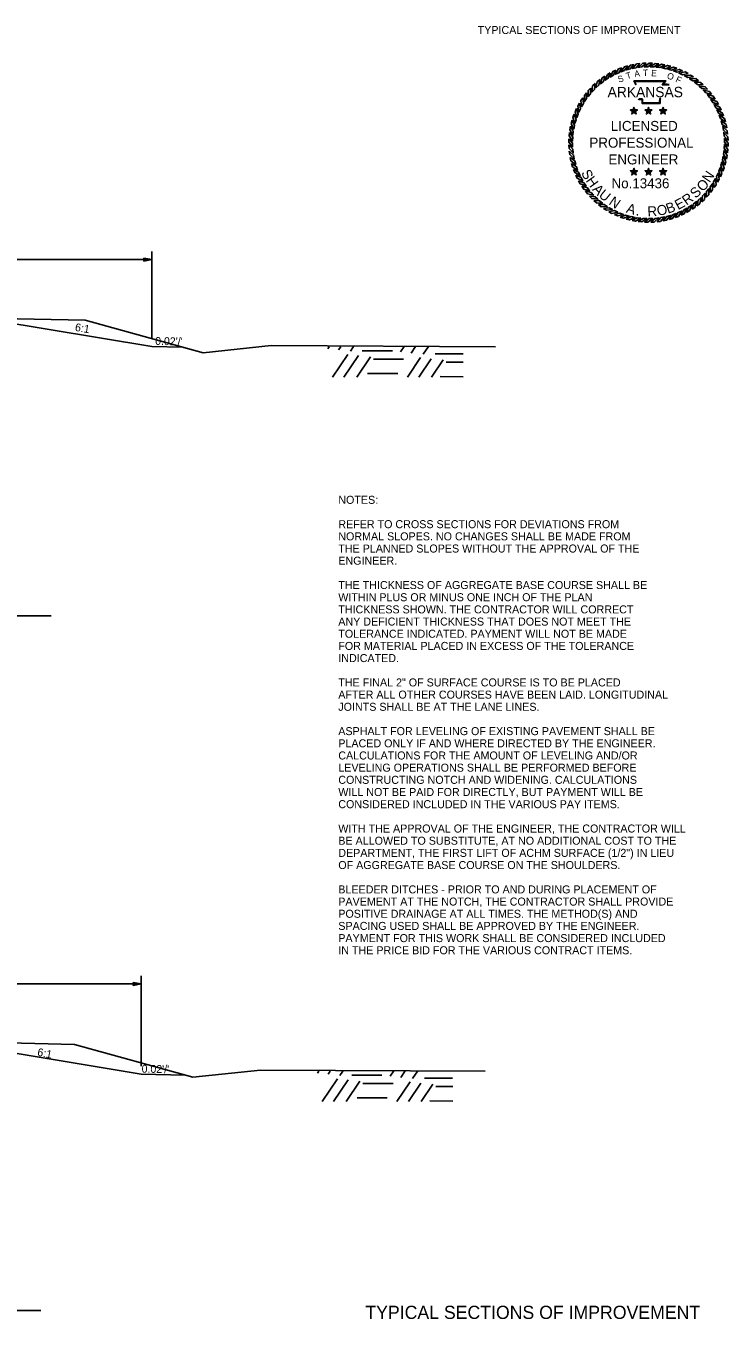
# Model space of a CAD drawing. Extents: x 1398565 to 1398920, y 1968324 to 1968581.
# Drawn here: x 1398867.3 to 1398919.9, y 1968480.4 to 1968577.4 of the extents above; entities that cross this region are included whole.
import ezdxf

# ---------------------------------------------------------------- set-up
doc = ezdxf.new("R2010")
doc.units = 0
for name, color, linetype in [('1', 7, 'Continuous'), ('10', 7, 'Continuous'), ('19', 7, 'Continuous'), ('42', 7, 'Continuous'), ('9', 7, 'Continuous'), ('G-ANNO-SYMB', 7, 'Continuous')]:
    doc.layers.add(name, color=color, linetype=linetype)

msp = doc.modelspace()

# ---------------------------------------------------------------- linework, layer by layer
at = {"layer": '19'}
for p, q in [((1398854.753, 1968559.857), (1398876.753, 1968559.857)), ((1398876.153, 1968559.752), (1398876.153, 1968559.962)), ((1398876.153, 1968559.962), (1398876.753, 1968559.857)), ((1398876.153, 1968559.907), (1398876.593, 1968559.872)), ((1398876.753, 1968559.857), (1398876.153, 1968559.752)), ((1398876.593, 1968559.842), (1398876.153, 1968559.802)), ((1398876.753, 1968553.948), (1398876.753, 1968560.457)), ((1398862.753, 1968555.674), (1398876.753, 1968553.34)), ((1398879.07, 1968553.294), (1398876.753, 1968553.34)), ((1398840.237, 1968533.167), (1398869.217, 1968533.167)), ((1398853.969, 1968505.564), (1398875.969, 1968505.564)), ((1398875.369, 1968505.459), (1398875.369, 1968505.669)), ((1398875.369, 1968505.669), (1398875.969, 1968505.564)), ((1398875.369, 1968505.614), (1398875.809, 1968505.579)), ((1398875.969, 1968505.564), (1398875.369, 1968505.459)), ((1398875.809, 1968505.549), (1398875.369, 1968505.509)), ((1398875.969, 1968499.403), (1398875.969, 1968506.164)), ((1398859.969, 1968501.461), (1398875.969, 1968498.794)), ((1398879.268, 1968498.728), (1398875.969, 1968498.794)), ((1398839.453, 1968481.09), (1398868.433, 1968481.09))]:
    msp.add_line(p, q, dxfattribs=at)
at = {"layer": '42'}
for points in [[(1398854.753, 1968555.787), (1398862.838, 1968555.503), (1398871.753, 1968555.327), (1398880.608, 1968552.866), (1398885.689, 1968553.408), (1398902.506, 1968553.319)], [(1398853.969, 1968501.494), (1398860.054, 1968501.291), (1398870.969, 1968501.034), (1398879.824, 1968498.574), (1398884.905, 1968499.115), (1398901.722, 1968499.026)]]:
    msp.add_lwpolyline(points, dxfattribs=at)
at = {"layer": '9'}
for p, q in [((1398889.943, 1968553.176), (1398890.047, 1968553.33)), ((1398890.292, 1968551.036), (1398891.446, 1968552.752)), ((1398890.741, 1968553.085), (1398890.907, 1968553.332)), ((1398891.631, 1968552.993), (1398891.859, 1968553.333)), ((1398892.521, 1968553.032), (1398894.783, 1968553.018)), ((1398895.394, 1968552.944), (1398895.66, 1968553.34)), ((1398896.192, 1968552.853), (1398896.52, 1968553.341)), ((1398897.082, 1968552.762), (1398897.473, 1968553.343)), ((1398897.972, 1968552.8), (1398900.078, 1968552.787)), ((1398891.152, 1968551.038), (1398892.243, 1968552.661)), ((1398892.105, 1968551.039), (1398893.133, 1968552.569)), ((1398893.356, 1968552.403), (1398895.618, 1968552.388)), ((1398895.906, 1968551.046), (1398896.897, 1968552.52)), ((1398896.766, 1968551.047), (1398897.694, 1968552.429)), ((1398897.718, 1968551.049), (1398898.584, 1968552.338)), ((1398898.807, 1968552.171), (1398900.079, 1968552.163)), ((1398892.913, 1968551.326), (1398895.175, 1968551.312)), ((1398898.364, 1968551.095), (1398900.081, 1968551.084)), ((1398889.159, 1968498.883), (1398889.263, 1968499.037)), ((1398889.508, 1968496.744), (1398890.662, 1968498.459)), ((1398889.957, 1968498.792), (1398890.123, 1968499.039)), ((1398890.847, 1968498.701), (1398891.075, 1968499.041)), ((1398891.737, 1968498.739), (1398893.999, 1968498.725)), ((1398894.611, 1968498.652), (1398894.876, 1968499.047)), ((1398895.408, 1968498.56), (1398895.736, 1968499.049)), ((1398896.298, 1968498.469), (1398896.689, 1968499.05)), ((1398897.188, 1968498.508), (1398899.294, 1968498.494)), ((1398890.368, 1968496.745), (1398891.459, 1968498.368)), ((1398891.321, 1968496.747), (1398892.349, 1968498.277)), ((1398892.572, 1968498.11), (1398894.834, 1968498.096)), ((1398895.122, 1968496.753), (1398896.113, 1968498.228)), ((1398895.982, 1968496.755), (1398896.911, 1968498.136)), ((1398896.934, 1968496.756), (1398897.801, 1968498.045)), ((1398898.023, 1968497.879), (1398899.295, 1968497.87)), ((1398892.129, 1968497.034), (1398894.391, 1968497.019)), ((1398897.58, 1968496.802), (1398899.297, 1968496.791))]:
    msp.add_line(p, q, dxfattribs=at)
at = {"layer": 'G-ANNO-SYMB'}
for points in [[(1398911.524, 1968574.067), (1398911.292, 1968573.957), (1398911.099, 1968573.543), (1398911.342, 1968573.676)], [(1398911.959, 1968574.242), (1398911.719, 1968574.15), (1398911.494, 1968573.752), (1398911.746, 1968573.866)], [(1398912.406, 1968574.382), (1398912.16, 1968574.309), (1398911.904, 1968573.93), (1398912.165, 1968574.024)], [(1398912.862, 1968574.486), (1398912.611, 1968574.433), (1398912.327, 1968574.076), (1398912.594, 1968574.149)], [(1398913.326, 1968574.555), (1398913.071, 1968574.522), (1398912.76, 1968574.187), (1398913.032, 1968574.239)], [(1398913.793, 1968574.586), (1398913.537, 1968574.573), (1398913.2, 1968574.264), (1398913.475, 1968574.295)], [(1398914.262, 1968574.581), (1398914.005, 1968574.589), (1398913.645, 1968574.307), (1398913.922, 1968574.316)], [(1398914.728, 1968574.54), (1398914.473, 1968574.567), (1398914.092, 1968574.315), (1398914.369, 1968574.302)], [(1398915.19, 1968574.461), (1398914.938, 1968574.509), (1398914.538, 1968574.287), (1398914.813, 1968574.252)], [(1398915.644, 1968574.347), (1398915.397, 1968574.414), (1398914.981, 1968574.224), (1398915.252, 1968574.168)], [(1398916.088, 1968574.198), (1398915.847, 1968574.284), (1398915.417, 1968574.127), (1398915.683, 1968574.05)], [(1398916.519, 1968574.014), (1398916.285, 1968574.119), (1398915.844, 1968573.996), (1398916.104, 1968573.898)], [(1398910.321, 1968573.347), (1398910.121, 1968573.186), (1398910.03, 1968572.738), (1398910.235, 1968572.925)], [(1398910.702, 1968573.618), (1398910.491, 1968573.474), (1398910.365, 1968573.034), (1398910.584, 1968573.204)], [(1398911.104, 1968573.859), (1398910.882, 1968573.731), (1398910.722, 1968573.303), (1398910.953, 1968573.455)], [(1398916.934, 1968573.797), (1398916.709, 1968573.92), (1398916.26, 1968573.832), (1398916.511, 1968573.714)], [(1398917.331, 1968573.548), (1398917.116, 1968573.688), (1398916.662, 1968573.636), (1398916.903, 1968573.499)], [(1398917.707, 1968573.268), (1398917.504, 1968573.425), (1398917.047, 1968573.409), (1398917.276, 1968573.253)], [(1398918.06, 1968572.96), (1398917.87, 1968573.132), (1398917.413, 1968573.152), (1398917.629, 1968572.979)], [(1398909.318, 1968572.366), (1398909.162, 1968572.163), (1398909.178, 1968571.706), (1398909.333, 1968571.935)], [(1398909.626, 1968572.719), (1398909.454, 1968572.529), (1398909.434, 1968572.072), (1398909.608, 1968572.288)], [(1398909.961, 1968573.047), (1398909.775, 1968572.871), (1398909.719, 1968572.417), (1398909.909, 1968572.619)], [(1398918.388, 1968572.625), (1398918.212, 1968572.812), (1398917.758, 1968572.868), (1398917.96, 1968572.678)], [(1398918.688, 1968572.266), (1398918.527, 1968572.466), (1398918.079, 1968572.557), (1398918.266, 1968572.352)], [(1398918.959, 1968571.884), (1398918.815, 1968572.096), (1398918.375, 1968572.222), (1398918.545, 1968572.003)], [(1398908.573, 1968571.178), (1398908.468, 1968570.944), (1398908.59, 1968570.503), (1398908.688, 1968570.763)], [(1398908.79, 1968571.593), (1398908.667, 1968571.368), (1398908.754, 1968570.919), (1398908.872, 1968571.17)], [(1398909.039, 1968571.99), (1398908.899, 1968571.775), (1398908.95, 1968571.321), (1398909.088, 1968571.562)], [(1398912.873, 1968570.998), (1398912.934, 1968571.083), (1398912.873, 1968571.271), (1398912.812, 1968571.083)], [(1398913.964, 1968570.998), (1398914.025, 1968571.083), (1398913.964, 1968571.271), (1398913.903, 1968571.083)], [(1398915.055, 1968570.998), (1398915.116, 1968571.083), (1398915.055, 1968571.271), (1398914.993, 1968571.083)], [(1398919.2, 1968571.482), (1398919.072, 1968571.705), (1398918.644, 1968571.865), (1398918.796, 1968571.633)], [(1398919.408, 1968571.062), (1398919.298, 1968571.294), (1398918.884, 1968571.487), (1398919.017, 1968571.245)], [(1398908.239, 1968570.303), (1398908.172, 1968570.056), (1398908.362, 1968569.64), (1398908.418, 1968569.911)], [(1398908.389, 1968570.747), (1398908.303, 1968570.506), (1398908.459, 1968570.076), (1398908.536, 1968570.342)], [(1398912.873, 1968570.998), (1398912.812, 1968571.083), (1398912.613, 1968571.083), (1398912.774, 1968570.966)], [(1398912.873, 1968570.998), (1398912.774, 1968570.966), (1398912.713, 1968570.778), (1398912.873, 1968570.894)], [(1398912.873, 1968570.998), (1398912.972, 1968570.966), (1398913.132, 1968571.083), (1398912.934, 1968571.083)], [(1398912.873, 1968570.998), (1398912.873, 1968570.894), (1398913.033, 1968570.778), (1398912.972, 1968570.966)], [(1398913.964, 1968570.998), (1398913.903, 1968571.083), (1398913.704, 1968571.083), (1398913.865, 1968570.966)], [(1398913.964, 1968570.998), (1398913.865, 1968570.966), (1398913.803, 1968570.778), (1398913.964, 1968570.894)], [(1398913.964, 1968570.998), (1398914.063, 1968570.966), (1398914.223, 1968571.083), (1398914.025, 1968571.083)], [(1398913.964, 1968570.998), (1398913.964, 1968570.894), (1398914.124, 1968570.778), (1398914.063, 1968570.966)], [(1398915.055, 1968570.998), (1398914.993, 1968571.083), (1398914.795, 1968571.083), (1398914.956, 1968570.966)], [(1398915.055, 1968570.998), (1398914.956, 1968570.966), (1398914.894, 1968570.778), (1398915.055, 1968570.894)], [(1398915.055, 1968570.998), (1398915.154, 1968570.966), (1398915.314, 1968571.083), (1398915.116, 1968571.083)], [(1398915.055, 1968570.998), (1398915.055, 1968570.894), (1398915.215, 1968570.778), (1398915.154, 1968570.966)], [(1398919.583, 1968570.628), (1398919.491, 1968570.867), (1398919.093, 1968571.093), (1398919.207, 1968570.84)], [(1398919.723, 1968570.181), (1398919.65, 1968570.427), (1398919.271, 1968570.683), (1398919.365, 1968570.422)], [(1398919.827, 1968569.724), (1398919.774, 1968569.975), (1398919.417, 1968570.26), (1398919.49, 1968569.992)], [(1398908.047, 1968569.387), (1398908.02, 1968569.132), (1398908.272, 1968568.751), (1398908.285, 1968569.028)], [(1398908.125, 1968569.849), (1398908.078, 1968569.597), (1398908.3, 1968569.197), (1398908.334, 1968569.472)], [(1398919.895, 1968569.261), (1398919.863, 1968569.515), (1398919.528, 1968569.827), (1398919.58, 1968569.555)], [(1398919.927, 1968568.793), (1398919.914, 1968569.049), (1398919.605, 1968569.387), (1398919.636, 1968569.111)], [(1398908.005, 1968568.921), (1398907.998, 1968568.664), (1398908.279, 1968568.304), (1398908.271, 1968568.581)], [(1398908, 1968568.452), (1398908.013, 1968568.196), (1398908.322, 1968567.859), (1398908.292, 1968568.134)], [(1398919.881, 1968567.858), (1398919.908, 1968568.113), (1398919.656, 1968568.495), (1398919.643, 1968568.218)], [(1398919.922, 1968568.325), (1398919.93, 1968568.581), (1398919.648, 1968568.942), (1398919.657, 1968568.665)], [(1398908.032, 1968567.985), (1398908.065, 1968567.73), (1398908.399, 1968567.419), (1398908.347, 1968567.691)], [(1398908.1, 1968567.521), (1398908.153, 1968567.27), (1398908.511, 1968566.986), (1398908.438, 1968567.253)], [(1398919.688, 1968566.942), (1398919.755, 1968567.19), (1398919.565, 1968567.606), (1398919.509, 1968567.334)], [(1398919.802, 1968567.396), (1398919.85, 1968567.649), (1398919.628, 1968568.048), (1398919.593, 1968567.773)], [(1398908.205, 1968567.065), (1398908.277, 1968566.819), (1398908.656, 1968566.563), (1398908.562, 1968566.824)], [(1398908.345, 1968566.618), (1398908.436, 1968566.378), (1398908.834, 1968566.153), (1398908.72, 1968566.405)], [(1398912.873, 1968566.43), (1398912.812, 1968566.514), (1398912.613, 1968566.514), (1398912.774, 1968566.398)], [(1398912.873, 1968566.43), (1398912.774, 1968566.398), (1398912.713, 1968566.21), (1398912.873, 1968566.326)], [(1398912.873, 1968566.43), (1398912.934, 1968566.514), (1398912.873, 1968566.703), (1398912.812, 1968566.514)], [(1398912.873, 1968566.43), (1398912.972, 1968566.398), (1398913.132, 1968566.514), (1398912.934, 1968566.514)], [(1398912.873, 1968566.43), (1398912.873, 1968566.326), (1398913.033, 1968566.21), (1398912.972, 1968566.398)], [(1398913.964, 1968566.43), (1398913.903, 1968566.514), (1398913.704, 1968566.514), (1398913.865, 1968566.398)], [(1398913.964, 1968566.43), (1398913.865, 1968566.398), (1398913.803, 1968566.21), (1398913.964, 1968566.326)], [(1398913.964, 1968566.43), (1398914.025, 1968566.514), (1398913.964, 1968566.703), (1398913.903, 1968566.514)], [(1398913.964, 1968566.43), (1398914.063, 1968566.398), (1398914.223, 1968566.514), (1398914.025, 1968566.514)], [(1398913.964, 1968566.43), (1398913.964, 1968566.326), (1398914.124, 1968566.21), (1398914.063, 1968566.398)], [(1398915.055, 1968566.43), (1398914.993, 1968566.514), (1398914.795, 1968566.514), (1398914.956, 1968566.398)], [(1398915.055, 1968566.43), (1398914.956, 1968566.398), (1398914.894, 1968566.21), (1398915.055, 1968566.326)], [(1398915.055, 1968566.43), (1398915.116, 1968566.514), (1398915.055, 1968566.703), (1398914.993, 1968566.514)], [(1398915.055, 1968566.43), (1398915.154, 1968566.398), (1398915.314, 1968566.514), (1398915.116, 1968566.514)], [(1398915.055, 1968566.43), (1398915.055, 1968566.326), (1398915.215, 1968566.21), (1398915.154, 1968566.398)], [(1398919.138, 1968565.652), (1398919.26, 1968565.877), (1398919.173, 1968566.326), (1398919.055, 1968566.075)], [(1398919.355, 1968566.067), (1398919.46, 1968566.301), (1398919.337, 1968566.742), (1398919.239, 1968566.483)], [(1398919.539, 1968566.498), (1398919.625, 1968566.74), (1398919.468, 1968567.169), (1398919.391, 1968566.903)], [(1398908.519, 1968566.183), (1398908.629, 1968565.951), (1398909.044, 1968565.758), (1398908.91, 1968566.001)], [(1398908.728, 1968565.763), (1398908.855, 1968565.541), (1398909.284, 1968565.381), (1398909.131, 1968565.612)], [(1398908.968, 1968565.361), (1398909.113, 1968565.15), (1398909.553, 1968565.024), (1398909.383, 1968565.243)], [(1398918.609, 1968564.879), (1398918.766, 1968565.083), (1398918.75, 1968565.54), (1398918.594, 1968565.31)], [(1398918.889, 1968565.255), (1398919.029, 1968565.47), (1398918.977, 1968565.925), (1398918.84, 1968565.684)], [(1398909.239, 1968564.98), (1398909.4, 1968564.78), (1398909.848, 1968564.689), (1398909.662, 1968564.894)], [(1398909.54, 1968564.62), (1398909.716, 1968564.434), (1398910.17, 1968564.378), (1398909.968, 1968564.568)], [(1398917.607, 1968563.898), (1398917.807, 1968564.059), (1398917.898, 1968564.507), (1398917.693, 1968564.321)], [(1398917.966, 1968564.199), (1398918.153, 1968564.375), (1398918.209, 1968564.829), (1398918.019, 1968564.627)], [(1398918.301, 1968564.526), (1398918.473, 1968564.717), (1398918.493, 1968565.174), (1398918.32, 1968564.957)], [(1398909.867, 1968564.285), (1398910.058, 1968564.113), (1398910.515, 1968564.093), (1398910.298, 1968564.267)], [(1398910.22, 1968563.977), (1398910.424, 1968563.821), (1398910.881, 1968563.837), (1398910.651, 1968563.992)], [(1398910.596, 1968563.698), (1398910.811, 1968563.558), (1398911.266, 1968563.61), (1398911.025, 1968563.747)], [(1398910.993, 1968563.449), (1398911.218, 1968563.326), (1398911.667, 1968563.413), (1398911.416, 1968563.531)], [(1398915.969, 1968563.004), (1398916.208, 1968563.095), (1398916.434, 1968563.493), (1398916.181, 1968563.379)], [(1398916.403, 1968563.178), (1398916.635, 1968563.288), (1398916.828, 1968563.703), (1398916.586, 1968563.569)], [(1398916.823, 1968563.387), (1398917.046, 1968563.514), (1398917.206, 1968563.943), (1398916.974, 1968563.79)], [(1398917.225, 1968563.627), (1398917.437, 1968563.772), (1398917.563, 1968564.212), (1398917.344, 1968564.042)], [(1398911.408, 1968563.232), (1398911.642, 1968563.127), (1398912.083, 1968563.249), (1398911.824, 1968563.347)], [(1398911.839, 1968563.048), (1398912.081, 1968562.962), (1398912.51, 1968563.118), (1398912.244, 1968563.195)], [(1398912.283, 1968562.898), (1398912.531, 1968562.831), (1398912.947, 1968563.021), (1398912.675, 1968563.077)], [(1398912.737, 1968562.784), (1398912.99, 1968562.737), (1398913.389, 1968562.959), (1398913.114, 1968562.993)], [(1398913.199, 1968562.706), (1398913.454, 1968562.679), (1398913.836, 1968562.931), (1398913.559, 1968562.944)], [(1398913.666, 1968562.664), (1398913.922, 1968562.657), (1398914.283, 1968562.938), (1398914.006, 1968562.93)], [(1398914.134, 1968562.659), (1398914.39, 1968562.672), (1398914.728, 1968562.981), (1398914.452, 1968562.951)], [(1398914.602, 1968562.691), (1398914.856, 1968562.724), (1398915.168, 1968563.058), (1398914.896, 1968563.006)], [(1398915.065, 1968562.759), (1398915.316, 1968562.812), (1398915.601, 1968563.17), (1398915.333, 1968563.097)], [(1398915.522, 1968562.864), (1398915.768, 1968562.936), (1398916.024, 1968563.315), (1398915.763, 1968563.221)]]:
    msp.add_lwpolyline(points, close=True, dxfattribs=at)
for points in [[(1398913.008, 1968572.953), (1398912.869, 1968573.254), (1398915.275, 1968573.255), (1398915.074, 1968573.003), (1398915.238, 1968573.005), (1398915.374, 1968573.007), (1398915.511, 1968572.992)], [(1398913.043, 1968572.969), (1398912.928, 1968573.216), (1398915.196, 1968573.217), (1398914.994, 1968572.964), (1398915.238, 1968572.967), (1398915.372, 1968572.968), (1398915.507, 1968572.954)], [(1398914.896, 1968571.944), (1398914.855, 1968571.911), (1398914.841, 1968571.861), (1398914.828, 1968571.736), (1398914.828, 1968571.57), (1398913.484, 1968571.57), (1398913.484, 1968571.794), (1398913.484, 1968571.844), (1398913.43, 1968571.861), (1398913.239, 1968571.861), (1398913.205, 1968571.913)], [(1398914.872, 1968571.974), (1398914.821, 1968571.933), (1398914.804, 1968571.868), (1398914.79, 1968571.738), (1398914.79, 1968571.608), (1398913.523, 1968571.608), (1398913.523, 1968571.794), (1398913.523, 1968571.873), (1398913.436, 1968571.899), (1398913.26, 1968571.899), (1398913.237, 1968571.934)]]:
    msp.add_lwpolyline(points, dxfattribs=at)

# ---------------------------------------------------------------- texts
at = {"layer": '1'}
msp.add_text('TYPICAL SECTIONS OF IMPROVEMENT', height=0.6, dxfattribs=at).set_placement((1398901.166, 1968576.769))
at = {"layer": '10'}
for rotation, p in [(350.53768, (1398870.972, 1968554.518)), (348.76163, (1398868.146, 1968500.193))]:
    msp.add_text('6:1', height=0.59, rotation=rotation, dxfattribs=at).set_placement(p)
at = {"layer": '19'}
for p in [(1398877.004, 1968553.467), (1398875.991, 1968498.921)]:
    msp.add_text("0.02'/'", height=0.59, rotation=358.85424, dxfattribs=at).set_placement(p)
for s, height, p in [('NOTES:', 0.6, (1398890.728, 1968541.553)), ('REFER TO CROSS SECTIONS FOR DEVIATIONS FROM', 0.6, (1398890.728, 1968539.728)), ('NORMAL SLOPES. NO CHANGES SHALL BE MADE FROM ', 0.6, (1398890.728, 1968538.816)), ('THE PLANNED SLOPES WITHOUT THE APPROVAL OF THE', 0.6, (1398890.728, 1968537.903)), ('ENGINEER.', 0.6, (1398890.728, 1968536.991)), ('THE THICKNESS OF AGGREGATE BASE COURSE SHALL BE', 0.6, (1398890.728, 1968535.166)), ('WITHIN PLUS OR MINUS ONE INCH OF THE PLAN ', 0.6, (1398890.728, 1968534.253)), ('THICKNESS SHOWN. THE CONTRACTOR WILL CORRECT', 0.6, (1398890.728, 1968533.341)), ('ANY DEFICIENT THICKNESS THAT DOES NOT MEET THE', 0.6, (1398890.728, 1968532.428)), ('TOLERANCE INDICATED. PAYMENT WILL NOT BE MADE', 0.6, (1398890.728, 1968531.516)), ('FOR MATERIAL PLACED IN EXCESS OF THE TOLERANCE', 0.6, (1398890.728, 1968530.603)), ('INDICATED.', 0.6, (1398890.728, 1968529.691)), ('AFTER ALL OTHER COURSES HAVE BEEN LAID. LONGITUDINAL', 0.6, (1398890.728, 1968526.953)), ('THE FINAL 2" OF SURFACE COURSE IS TO BE PLACED', 0.6, (1398890.728, 1968527.866)), ('JOINTS SHALL BE AT THE LANE LINES.', 0.6, (1398890.728, 1968526.041)), ('ASPHALT FOR LEVELING OF EXISTING PAVEMENT SHALL BE', 0.6, (1398890.728, 1968524.216)), ('PLACED ONLY IF AND WHERE DIRECTED BY THE ENGINEER.', 0.6, (1398890.728, 1968523.303)), ('CALCULATIONS FOR THE AMOUNT OF LEVELING AND/OR', 0.6, (1398890.728, 1968522.391)), ('LEVELING OPERATIONS SHALL BE PERFORMED BEFORE ', 0.6, (1398890.728, 1968521.478)), ('CONSTRUCTING NOTCH AND WIDENING. CALCULATIONS', 0.6, (1398890.728, 1968520.566)), ('WILL NOT BE PAID FOR DIRECTLY, BUT PAYMENT WILL BE', 0.6, (1398890.728, 1968519.653)), ('CONSIDERED INCLUDED IN THE VARIOUS PAY ITEMS.', 0.6, (1398890.728, 1968518.741)), ('WITH THE APPROVAL OF THE ENGINEER, THE CONTRACTOR WILL', 0.6, (1398890.728, 1968516.916)), ('BE ALLOWED TO SUBSTITUTE, AT NO ADDITIONAL COST TO THE', 0.6, (1398890.728, 1968516.003)), ('DEPARTMENT, THE FIRST LIFT OF ACHM SURFACE (1/2") IN LIEU', 0.6, (1398890.728, 1968515.091)), ('OF AGGREGATE BASE COURSE ON THE SHOULDERS.', 0.6, (1398890.728, 1968514.178)), ('BLEEDER DITCHES - PRIOR TO AND DURING PLACEMENT OF', 0.6, (1398890.728, 1968512.353)), ('PAVEMENT AT THE NOTCH, THE CONTRACTOR SHALL PROVIDE', 0.6, (1398890.728, 1968511.441)), ('POSITIVE DRAINAGE AT ALL TIMES. THE METHOD(S) AND', 0.6, (1398890.728, 1968510.528)), ('SPACING USED SHALL BE APPROVED BY THE ENGINEER.', 0.6, (1398890.728, 1968509.616)), ('PAYMENT FOR THIS WORK SHALL BE CONSIDERED INCLUDED', 0.6, (1398890.728, 1968508.703)), ('IN THE PRICE BID FOR THE VARIOUS CONTRACT ITEMS.', 0.6, (1398890.728, 1968507.791)), ('TYPICAL SECTIONS OF IMPROVEMENT', 0.98999, (1398892.754, 1968480.457))]:
    msp.add_text(s, height=height, dxfattribs=at).set_placement(p)
at = {"layer": 'G-ANNO-SYMB'}
for s, height, rotation, p in [('T', 0.475, 1.47887, (1398913.548, 1968573.626)), ('E', 0.475, 356.67203, (1398914.155, 1968573.612)), ('S', 0.475, 19.77256, (1398911.755, 1968573.111)), ('T', 0.475, 16.90148, (1398912.358, 1968573.382)), ('A', 0.475, 8.67877, (1398912.935, 1968573.532)), ('O', 0.475, 341.2218, (1398915.308, 1968573.449)), ('F', 0.475, 335.36282, (1398915.947, 1968573.199)), ('ARKANSAS', 0.7747, 360, (1398910.902, 1968572.031)), ('LICENSED', 0.75, 360, (1398911.142, 1968569.502)), ('PROFESSIONAL', 0.75, 360, (1398909.535, 1968568.248)), ('ENGINEER', 0.75, 360, (1398910.964, 1968566.993)), ('S', 0.75, 298.16364, (1398908.896, 1968566.363)), ('N', 0.75, 56.10067, (1398918.538, 1968565.579)), ('H', 0.75, 305.61905, (1398909.238, 1968565.775)), ('A', 0.75, 313.44722, (1398909.714, 1968565.091)), ('No.13436', 0.747, 360, (1398911.2, 1968565.206)), ('O', 0.75, 44.77573, (1398918.017, 1968564.904)), ('U', 0.75, 320.90262, (1398910.181, 1968564.602)), ('N', 0.75, 324.93262, (1398910.937, 1968564.043)), ('E', 0.75, 27.83149, (1398916.178, 1968563.565)), ('R', 0.75, 35.65967, (1398916.812, 1968563.897)), ('S', 0.75, 43.48784, (1398917.502, 1968564.407)), ('A', 0.75, 343.09908, (1398912.245, 1968563.4)), ('R', 0.75, 3.22866, (1398913.901, 1968563.086)), ('O', 0.75, 11.42961, (1398914.669, 1968563.135)), ('B', 0.75, 18.88501, (1398915.421, 1968563.294)), ('.', 0.75, 351.30002, (1398912.982, 1968563.181))]:
    msp.add_text(s, height=height, rotation=rotation, dxfattribs=at).set_placement(p)

doc.saveas('drawing.dxf')
